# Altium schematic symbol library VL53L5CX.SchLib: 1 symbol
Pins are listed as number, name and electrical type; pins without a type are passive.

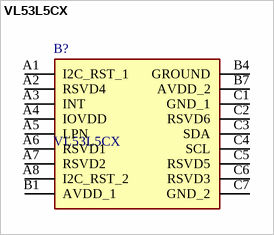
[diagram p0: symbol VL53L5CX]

## VL53L5CX
designator B?
Time-of-Flight 8x8 multizone ranging sensor with wide field of view; Manufacturer_Name: STMicroelectronics; Geometry.Height: 1.55mm
footprint VL53L5CX
pins: A1 I2C_RST_1, A2 RSVD4, A3 INT, A4 IOVDD, A5 LPN, A6 RSVD1, A7 RSVD2, A8 I2C_RST_2, B1 AVDD_1, B4 GROUND, B7 AVDD_2, C1 GND_1, C2 RSVD6, C3 SDA, C4 SCL, C5 RSVD5, C6 RSVD3, C7 GND_2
